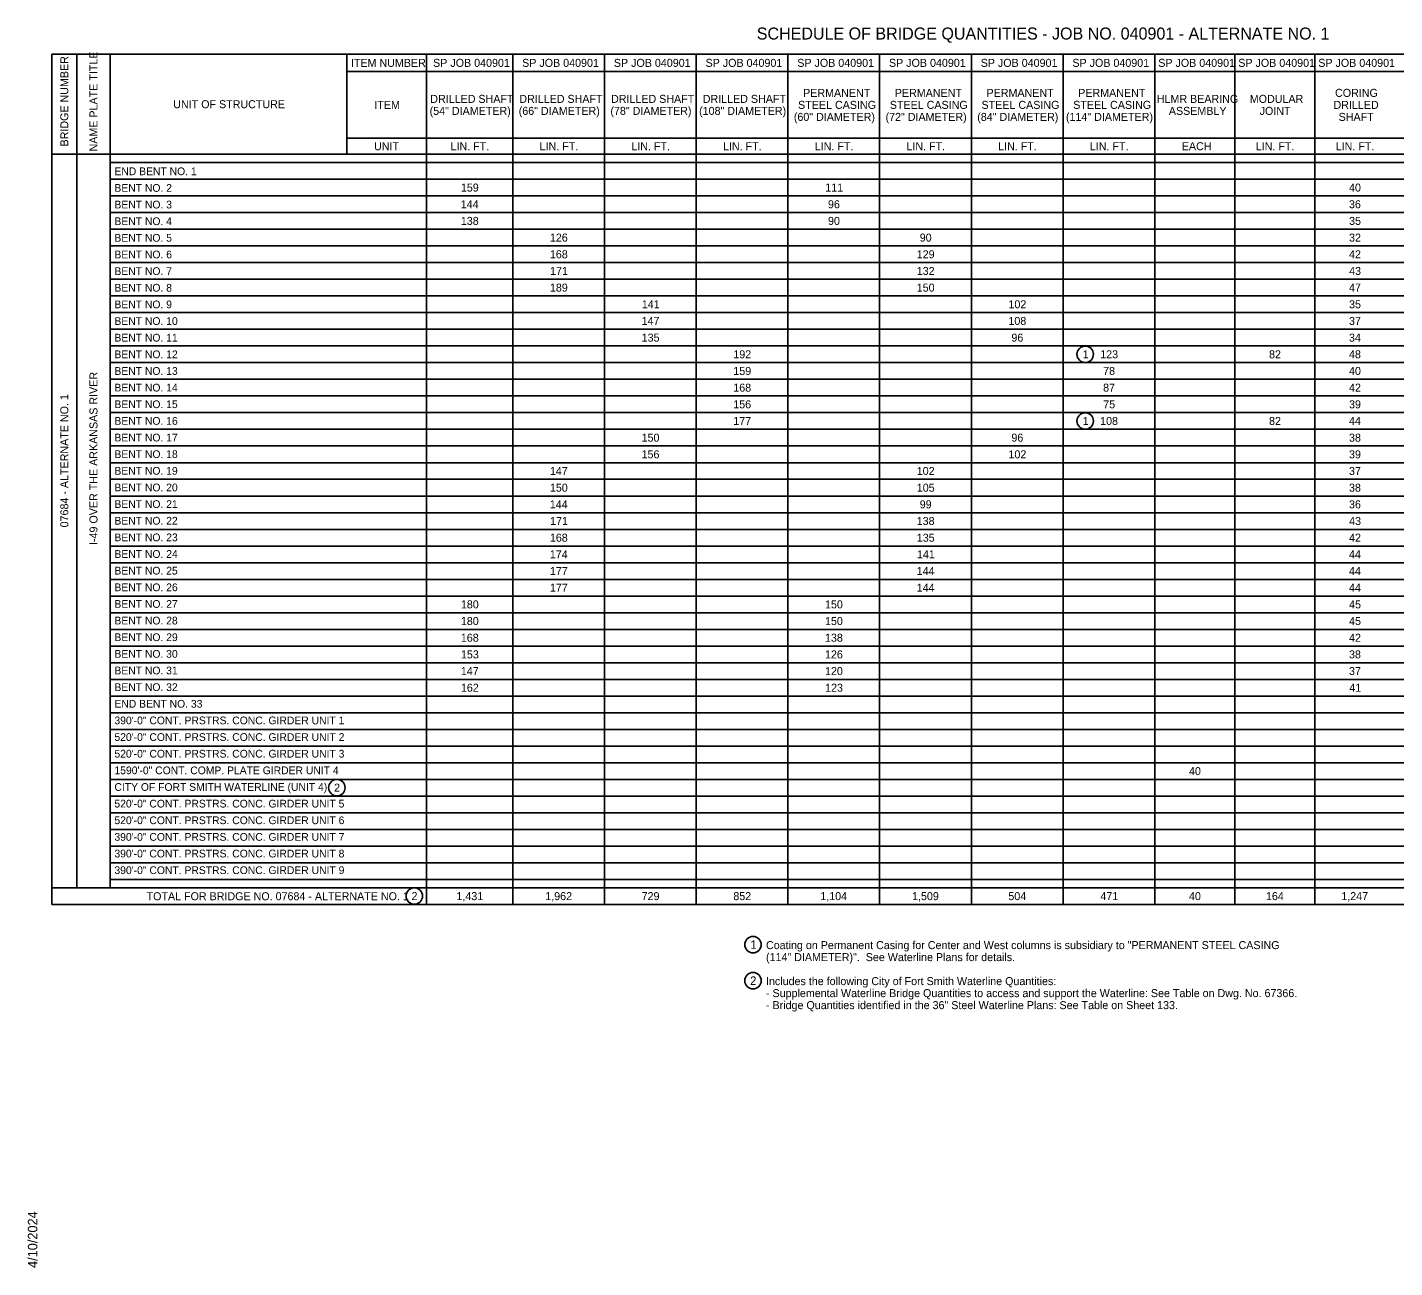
# Model space of a CAD drawing. Extents: x 0.06 to 1.36, y 0.04 to 0.85.
# Drawn here: x 0.06 to 0.914, y 0.079 to 0.854 of the extents above; entities that cross this region are included whole.
import ezdxf

# ---------------------------------------------------------------- set-up
doc = ezdxf.new("R2010")
doc.units = 0
for name, color, linetype in [('R_ROW', 7, 'Continuous'), ('R_Shade By Others', 7, 'Continuous'), ('R_Survey Control', 7, 'Continuous'), ('R_Wall', 7, 'Continuous')]:
    doc.layers.add(name, color=color, linetype=linetype)

msp = doc.modelspace()

# ---------------------------------------------------------------- linework, layer by layer
at = {"layer": 'R_Survey Control'}
for p, q in [((0.07508, 0.3057), (0.07508, 0.83695)), ((0.07508, 0.83695), (1.30054, 0.83695)), ((0.09071, 0.31612), (0.09071, 0.83695)), ((0.11154, 0.31612), (0.11154, 0.83695)), ((0.11154, 0.77445), (0.11154, 0.83695)), ((0.2593, 0.77445), (0.2593, 0.83695)), ((0.30915, 0.83695), (0.30915, 0.3057)), ((0.36311, 0.83695), (0.36311, 0.3057)), ((0.4204, 0.83695), (0.4204, 0.3057)), ((0.47769, 0.83695), (0.47769, 0.3057)), ((0.53498, 0.83695), (0.53498, 0.3057)), ((0.59227, 0.83695), (0.59227, 0.3057)), ((0.64957, 0.83695), (0.64957, 0.3057)), ((0.70686, 0.83695), (0.70686, 0.3057)), ((0.76415, 0.83695), (0.76415, 0.3057)), ((0.81414, 0.83695), (0.81414, 0.3057)), ((0.86412, 0.83695), (0.86412, 0.3057)), ((0.2593, 0.78445), (1.30054, 0.78445)), ((0.07508, 0.77445), (1.30054, 0.77445)), ((0.11154, 0.76924), (1.30054, 0.76924)), ((0.11154, 0.75883), (1.30054, 0.75883)), ((0.11154, 0.74841), (1.30054, 0.74841)), ((0.11154, 0.73799), (1.30054, 0.73799)), ((0.11154, 0.72758), (1.30054, 0.72758)), ((0.11154, 0.71716), (1.30054, 0.71716)), ((0.11154, 0.70674), (1.30054, 0.70674)), ((0.11154, 0.69633), (1.30054, 0.69633)), ((0.11154, 0.68591), (1.30054, 0.68591)), ((0.11154, 0.67549), (1.30054, 0.67549)), ((0.11154, 0.66508), (1.30054, 0.66508)), ((0.11154, 0.65466), (1.30054, 0.65466)), ((0.11154, 0.64424), (1.30054, 0.64424)), ((0.11154, 0.63383), (1.30054, 0.63383)), ((0.11154, 0.62341), (1.30054, 0.62341)), ((0.11154, 0.61299), (1.30054, 0.61299)), ((0.11154, 0.60258), (1.30054, 0.60258)), ((0.11154, 0.59216), (1.30054, 0.59216)), ((0.11154, 0.58174), (1.30054, 0.58174)), ((0.11154, 0.57133), (1.30054, 0.57133)), ((0.11154, 0.56091), (1.30054, 0.56091)), ((0.11154, 0.55049), (1.30054, 0.55049)), ((0.11154, 0.54008), (1.30054, 0.54008)), ((0.11154, 0.52966), (1.30054, 0.52966)), ((0.11154, 0.51924), (1.30054, 0.51924)), ((0.11154, 0.50883), (1.30054, 0.50883)), ((0.11154, 0.49841), (1.30054, 0.49841)), ((0.11154, 0.48799), (1.30054, 0.48799)), ((0.11154, 0.47758), (1.30054, 0.47758)), ((0.11154, 0.46716), (1.30054, 0.46716)), ((0.11154, 0.45674), (1.30054, 0.45674)), ((0.11154, 0.44633), (1.30054, 0.44633)), ((0.11154, 0.43591), (1.30054, 0.43591)), ((0.11154, 0.42549), (1.30054, 0.42549)), ((0.11154, 0.41508), (1.30054, 0.41508)), ((0.11154, 0.40466), (1.30054, 0.40466)), ((0.11154, 0.39424), (1.30054, 0.39424)), ((0.11154, 0.38383), (1.30054, 0.38383)), ((0.11154, 0.37341), (1.30054, 0.37341)), ((0.11154, 0.36299), (1.30054, 0.36299)), ((0.11154, 0.35258), (1.30054, 0.35258)), ((0.11154, 0.34216), (1.30054, 0.34216)), ((0.11154, 0.33174), (1.30054, 0.33174)), ((0.07508, 0.31612), (1.30054, 0.31612)), ((0.11154, 0.32133), (1.30054, 0.32133)), ((0.07508, 0.3057), (1.30054, 0.3057))]:
    msp.add_line(p, q, dxfattribs=at)
msp.add_lwpolyline([(0.2593, 0.82612), (0.30758, 0.82612), (0.36154, 0.82612), (0.40321, 0.82612), (0.44487, 0.82612), (0.49175, 0.82612), (0.52821, 0.82612), (0.58029, 0.82612), (0.64019, 0.82612), (0.7079, 0.82612), (0.75998, 0.82612), (0.81206, 0.82612), (0.85894, 0.82612), (0.86623, 0.82612), (0.92873, 0.82612), (0.99644, 0.82612), (1.06415, 0.82612), (1.11623, 0.82612), (1.16831, 0.82612), (1.30054, 0.82612)], dxfattribs=at)
at = {"layer": 'R_Wall'}
for p, q in [((0.07508, 0.77445), (0.09071, 0.77445)), ((0.09071, 0.77445), (0.11154, 0.77445))]:
    msp.add_line(p, q, dxfattribs=at)
for centre in [(0.7207, 0.64945), (0.7207, 0.60779), (0.25316, 0.37868), (0.30155, 0.31097), (0.51317, 0.28059), (0.51317, 0.25809)]:
    msp.add_circle(centre, 0.00515, dxfattribs=at)

# ---------------------------------------------------------------- texts
at = {"layer": 'R_ROW'}
msp.add_text('SCHEDULE OF BRIDGE QUANTITIES - JOB NO. 040901 - ALTERNATE NO. 1', height=0.0075, dxfattribs=at).set_placement((0.51549, 0.84612))
at = {"layer": 'R_Shade By Others'}
msp.add_text('4/10/2024', height=0.00595, rotation=89.99995, dxfattribs=at).set_placement((0.06607, 0.0786))
at = {"layer": 'R_Survey Control'}
for s, p in [('NAME PLATE TITLE', (0.10362, 0.77619)), ('BRIDGE NUMBER', (0.0854, 0.77929)), ('I-49 OVER THE ARKANSAS RIVER', (0.10362, 0.53031)), ('07684 - ALTERNATE NO. 1', (0.0854, 0.54132))]:
    msp.add_text(s, height=0.005, rotation=90, dxfattribs=at).set_placement(p)
for s, height, p in [('ITEM NUMBER', 0.005, (0.26194, 0.82904)), ('SP JOB 040901', 0.005, (0.3133, 0.82904)), ('SP JOB 040901', 0.005, (0.36892, 0.82904)), ('SP JOB 040901', 0.005, (0.42622, 0.82904)), ('SP JOB 040901', 0.005, (0.48351, 0.82904)), ('SP JOB 040901', 0.005, (0.5408, 0.82904)), ('SP JOB 040901', 0.005, (0.59809, 0.82904)), ('SP JOB 040901', 0.005, (0.65538, 0.82904)), ('SP JOB 040901', 0.005, (0.71267, 0.82904)), ('SP JOB 040901', 0.005, (0.76631, 0.82904)), ('SP JOB 040901', 0.005, (0.8163, 0.82904)), ('SP JOB 040901', 0.005, (0.86628, 0.82904)), ('DRILLED SHAFT', 0.005, (0.31153, 0.80654)), ('DRILLED SHAFT', 0.005, (0.36715, 0.80654)), ('DRILLED SHAFT', 0.005, (0.42444, 0.80654)), ('DRILLED SHAFT', 0.005, (0.48174, 0.80654)), ('PERMANENT', 0.005, (0.54443, 0.81029)), ('PERMANENT', 0.005, (0.60172, 0.81029)), ('PERMANENT', 0.005, (0.65901, 0.81029)), ('PERMANENT', 0.005, (0.71631, 0.81029)), ('HLMR BEARING', 0.005, (0.76539, 0.80654)), ('MODULAR', 0.005, (0.8235, 0.80654)), ('CORING', 0.005, (0.87677, 0.81029)), ('UNIT OF STRUCTURE', 0.005, (0.15095, 0.8032)), ('ITEM', 0.005, (0.27661, 0.80279)), ('(54" DIAMETER)', 0.005, (0.31114, 0.79904)), ('(66" DIAMETER)', 0.005, (0.36677, 0.79904)), ('(78" DIAMETER)', 0.005, (0.42406, 0.79904)), ('(108" DIAMETER)', 0.005, (0.47948, 0.79904)), ('STEEL CASING', 0.005, (0.54131, 0.80279)), ('STEEL CASING', 0.005, (0.59861, 0.80279)), ('STEEL CASING', 0.005, (0.6559, 0.80279)), ('STEEL CASING', 0.005, (0.71319, 0.80279)), ('ASSEMBLY', 0.005, (0.77293, 0.79904)), ('JOINT', 0.005, (0.82968, 0.79904)), ('DRILLED', 0.005, (0.87579, 0.80279)), ('(60" DIAMETER)', 0.005, (0.53864, 0.79529)), ('(72" DIAMETER)', 0.005, (0.59594, 0.79529)), ('(84" DIAMETER)', 0.005, (0.65323, 0.79529)), ('(114" DIAMETER)', 0.005, (0.70864, 0.79529)), ('SHAFT', 0.005, (0.87901, 0.79529)), ('UNIT', 0.005, (0.27638, 0.77695)), ('LIN. FT.', 0.005, (0.32421, 0.77695)), ('LIN. FT.', 0.005, (0.37983, 0.77695)), ('LIN. FT.', 0.005, (0.43712, 0.77695)), ('LIN. FT.', 0.005, (0.49441, 0.77695)), ('LIN. FT.', 0.005, (0.55171, 0.77695)), ('LIN. FT.', 0.005, (0.609, 0.77695)), ('LIN. FT.', 0.005, (0.66629, 0.77695)), ('LIN. FT.', 0.005, (0.72358, 0.77695)), ('EACH', 0.005, (0.78102, 0.77695)), ('LIN. FT.', 0.005, (0.82721, 0.77695)), ('LIN. FT.', 0.005, (0.87718, 0.77695)), ('END BENT NO. 1', 0.0048358, (0.11421, 0.76137)), ('BENT NO. 2', 0.004836, (0.11421, 0.75098)), ('159', 0.005, (0.33064, 0.75112)), ('111', 0.005, (0.55828, 0.75112)), ('40', 0.005, (0.8855, 0.75112)), ('BENT NO. 3', 0.004836, (0.11421, 0.74058)), ('144', 0.005, (0.33058, 0.7407)), ('96', 0.005, (0.55999, 0.7407)), ('36', 0.005, (0.88547, 0.7407)), ('BENT NO. 4', 0.004836, (0.11421, 0.73018)), ('138', 0.005, (0.33062, 0.73029)), ('90', 0.005, (0.56001, 0.73029)), ('35', 0.005, (0.88554, 0.73029)), ('BENT NO. 5', 0.004836, (0.11421, 0.71979)), ('126', 0.005, (0.38624, 0.71987)), ('90', 0.005, (0.61731, 0.71987)), ('32', 0.005, (0.88551, 0.71987)), ('BENT NO. 6', 0.004836, (0.11421, 0.70939)), ('168', 0.005, (0.38625, 0.70945)), ('129', 0.005, (0.61543, 0.70945)), ('42', 0.005, (0.88551, 0.70945)), ('BENT NO. 7', 0.004836, (0.11421, 0.69899)), ('171', 0.005, (0.3864, 0.69904)), ('132', 0.005, (0.61544, 0.69904)), ('43', 0.005, (0.88556, 0.69904)), ('BENT NO. 8', 0.004836, (0.11421, 0.6886)), ('189', 0.005, (0.38627, 0.68862)), ('150', 0.005, (0.61543, 0.68862)), ('47', 0.005, (0.88548, 0.68862)), ('BENT NO. 9', 0.004836, (0.11421, 0.6782)), ('141', 0.005, (0.44369, 0.6782)), ('102', 0.005, (0.67274, 0.6782)), ('35', 0.005, (0.88554, 0.6782)), ('BENT NO. 10', 0.0048358, (0.11421, 0.6678)), ('147', 0.005, (0.44354, 0.66779)), ('108', 0.005, (0.67271, 0.66779)), ('37', 0.005, (0.88548, 0.66779)), ('BENT NO. 11', 0.0048358, (0.11421, 0.65741)), ('135', 0.005, (0.44359, 0.65737)), ('96', 0.005, (0.67457, 0.65737)), ('34', 0.005, (0.88545, 0.65737)), ('BENT NO. 12', 0.0048358, (0.11421, 0.64701)), ('192', 0.005, (0.50086, 0.64695)), ('123', 0.005, (0.73007, 0.64695)), ('82', 0.005, (0.83553, 0.64695)), ('48', 0.005, (0.88548, 0.64695)), ('BENT NO. 13', 0.0048358, (0.11421, 0.63661)), ('159', 0.005, (0.50085, 0.63654)), ('78', 0.005, (0.73187, 0.63654)), ('40', 0.005, (0.8855, 0.63654)), ('BENT NO. 14', 0.0048358, (0.11421, 0.62621)), ('168', 0.005, (0.50083, 0.62612)), ('87', 0.005, (0.73187, 0.62612)), ('42', 0.005, (0.88551, 0.62612)), ('BENT NO. 15', 0.0048358, (0.11421, 0.61582)), ('156', 0.005, (0.50082, 0.6157)), ('75', 0.005, (0.73193, 0.6157)), ('39', 0.005, (0.8855, 0.6157)), ('BENT NO. 16', 0.0048358, (0.11421, 0.60542)), ('177', 0.005, (0.50083, 0.60529)), ('108', 0.005, (0.73, 0.60529)), ('82', 0.005, (0.83553, 0.60529)), ('44', 0.005, (0.88545, 0.60529)), ('BENT NO. 17', 0.0048358, (0.11421, 0.59502)), ('150', 0.005, (0.44355, 0.59487)), ('96', 0.005, (0.67457, 0.59487)), ('38', 0.005, (0.88548, 0.59487)), ('BENT NO. 18', 0.0048358, (0.11421, 0.58463)), ('156', 0.005, (0.44353, 0.58445)), ('102', 0.005, (0.67274, 0.58445)), ('39', 0.005, (0.8855, 0.58445)), ('BENT NO. 19', 0.0048358, (0.11421, 0.57423)), ('147', 0.005, (0.38625, 0.57404)), ('102', 0.005, (0.61544, 0.57404)), ('37', 0.005, (0.88548, 0.57404)), ('BENT NO. 20', 0.0048358, (0.11421, 0.56383)), ('150', 0.005, (0.38626, 0.56362)), ('105', 0.005, (0.61547, 0.56362)), ('38', 0.005, (0.88548, 0.56362)), ('BENT NO. 21', 0.0048358, (0.11421, 0.55344)), ('144', 0.005, (0.38621, 0.5532)), ('99', 0.005, (0.61731, 0.5532)), ('36', 0.005, (0.88547, 0.5532)), ('BENT NO. 22', 0.0048358, (0.11421, 0.54304)), ('171', 0.005, (0.3864, 0.54279)), ('138', 0.005, (0.61541, 0.54279)), ('43', 0.005, (0.88556, 0.54279)), ('BENT NO. 23', 0.0048358, (0.11421, 0.53264)), ('168', 0.005, (0.38625, 0.53237)), ('135', 0.005, (0.61547, 0.53237)), ('42', 0.005, (0.88551, 0.53237)), ('BENT NO. 24', 0.0048358, (0.11421, 0.52225)), ('174', 0.005, (0.38621, 0.52195)), ('141', 0.005, (0.61557, 0.52195)), ('44', 0.005, (0.88545, 0.52195)), ('BENT NO. 25', 0.0048358, (0.11421, 0.51185)), ('177', 0.005, (0.38625, 0.51154)), ('144', 0.005, (0.61538, 0.51154)), ('44', 0.005, (0.88545, 0.51154)), ('BENT NO. 26', 0.0048358, (0.11421, 0.50145)), ('177', 0.005, (0.38625, 0.50112)), ('144', 0.005, (0.61538, 0.50112)), ('44', 0.005, (0.88545, 0.50112)), ('BENT NO. 27', 0.0048358, (0.11421, 0.49105)), ('180', 0.005, (0.33064, 0.4907)), ('150', 0.005, (0.55814, 0.4907)), ('45', 0.005, (0.88554, 0.4907)), ('BENT NO. 28', 0.0048358, (0.11421, 0.48066)), ('180', 0.005, (0.33064, 0.48029)), ('150', 0.005, (0.55814, 0.48029)), ('45', 0.005, (0.88554, 0.48029)), ('BENT NO. 29', 0.0048358, (0.11421, 0.47026)), ('168', 0.005, (0.33062, 0.46987)), ('138', 0.005, (0.55812, 0.46987)), ('42', 0.005, (0.88551, 0.46987)), ('BENT NO. 30', 0.0048358, (0.11421, 0.45986)), ('153', 0.005, (0.33069, 0.45945)), ('126', 0.005, (0.55811, 0.45945)), ('38', 0.005, (0.88548, 0.45945)), ('BENT NO. 31', 0.0048358, (0.11421, 0.44947)), ('147', 0.005, (0.33062, 0.44904)), ('120', 0.005, (0.55814, 0.44904)), ('37', 0.005, (0.88548, 0.44904)), ('BENT NO. 32', 0.0048358, (0.11421, 0.43907)), ('162', 0.005, (0.33065, 0.43862)), ('123', 0.005, (0.55819, 0.43862)), ('41', 0.005, (0.88564, 0.43862)), ('END BENT NO. 33', 0.0048358, (0.11421, 0.42867)), ('390\'-0" CONT. PRSTRS. CONC. GIRDER UNIT 1', 0.0048358, (0.11421, 0.41828)), ('520\'-0" CONT. PRSTRS. CONC. GIRDER UNIT 2', 0.0048358, (0.11421, 0.40788)), ('520\'-0" CONT. PRSTRS. CONC. GIRDER UNIT 3', 0.0048358, (0.11421, 0.39748)), ('1590\'-0" CONT. COMP. PLATE GIRDER UNIT 4', 0.0048358, (0.11421, 0.38708)), ('40', 0.005, (0.78553, 0.38654)), ('CITY OF FORT SMITH WATERLINE (UNIT 4)', 0.0048358, (0.11421, 0.37669)), ('520\'-0" CONT. PRSTRS. CONC. GIRDER UNIT 5', 0.0048358, (0.11421, 0.36629)), ('520\'-0" CONT. PRSTRS. CONC. GIRDER UNIT 6', 0.0048358, (0.11421, 0.35589)), ('390\'-0" CONT. PRSTRS. CONC. GIRDER UNIT 7', 0.0048358, (0.11421, 0.3455)), ('390\'-0" CONT. PRSTRS. CONC. GIRDER UNIT 8', 0.0048358, (0.11421, 0.3351)), ('390\'-0" CONT. PRSTRS. CONC. GIRDER UNIT 9', 0.0048358, (0.11421, 0.3247)), ('TOTAL FOR BRIDGE NO. 07684 - ALTERNATE NO. 1', 0.005, (0.13429, 0.30834)), ('1,431', 0.005, (0.32786, 0.30841)), ('1,962', 0.005, (0.38336, 0.30841)), ('729', 0.005, (0.44356, 0.30841)), ('852', 0.005, (0.50086, 0.30841)), ('1,104', 0.005, (0.55517, 0.30841)), ('1,509', 0.005, (0.61252, 0.30841)), ('504', 0.005, (0.67267, 0.30841)), ('471', 0.005, (0.73015, 0.30841)), ('40', 0.005, (0.78553, 0.30841)), ('164', 0.005, (0.83359, 0.30841)), ('1,247', 0.005, (0.88069, 0.30841))]:
    msp.add_text(s, height=height, dxfattribs=at).set_placement(p)
at = {"layer": 'R_Wall'}
for s, height, p in [('1', 0.005, (0.71911, 0.64695)), ('1', 0.005, (0.71911, 0.60529)), ('2', 0.005, (0.25143, 0.37618)), ('2', 0.005, (0.29982, 0.30847)), ('1', 0.00521, (0.51151, 0.27799)), ('Coating on Permanent Casing for Center and West columns is subsidiary to "PERMANENT STEEL CASING ', 0.005, (0.52126, 0.27781)), ('(114" DIAMETER)".  See Waterline Plans for details.', 0.005, (0.52126, 0.27031)), ('2', 0.00521, (0.51138, 0.25549)), ('Includes the following City of Fort Smith Waterline Quantities:', 0.005, (0.52126, 0.25531)), ('- Supplemental Waterline Bridge Quantities to access and support the Waterline: See Table on Dwg. No. 67366.', 0.005, (0.52126, 0.24781)), ('- Bridge Quantities identified in the 36" Steel Waterline Plans: See Table on Sheet 133.', 0.005, (0.52126, 0.24031))]:
    msp.add_text(s, height=height, dxfattribs=at).set_placement(p)

doc.saveas('drawing.dxf')
